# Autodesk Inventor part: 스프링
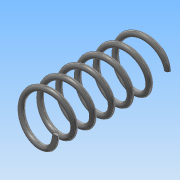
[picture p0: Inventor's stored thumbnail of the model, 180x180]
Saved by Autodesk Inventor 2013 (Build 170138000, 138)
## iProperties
Created: 2016-04
Part Number: 스프링
Material: 강철, 탄소
Document SubType Name: Modeling
Designer: Administrator
Density: 7.87 g/cm^3
Mass: 7.38127 g
Surface Area: 18.9917 cm^2
Volume: 0.937899 cm^3
Author: Administrator
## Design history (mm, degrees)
sketch "스케치1"
  geometry: L1 (0, 0)-(0, 42); L2 (0, 42)-(25.727, 42); C1 r 1 at (8, 0)
  constraints: 4 end point, 1 centre point, 1 horizontal alignment, 1 perpendicular, 1 vertical
  dimensions: "d0" = 42 distance of L1.start L1.end (derived); "d1" = 2 diameter of C1; "d2" = 16 diameter of C1.centre L1
feature "코일1" sketch "스케치1" pitch "d3" = 10; turns "d5" = 6; dims "d4" = 42 (= d0), "d6" = 0, angle "d7" = 90 deg, angle "d8" = 90 deg, "d9" = 0, "d10" = 0
sketch "스케치2"
  geometry: L1 (-10, 42)-(10, 42); L2 (10, 42)-(10, 0); L3 (10, 0)-(-10, 0); L4 (-10, 0)-(-10, 42); 2 further points
  constraints: 8 end point, 2 parallel, 1 coincident, 1 horizontal, 1 midpoint, 1 perpendicular
  dimensions: "d11" = 42 distance between parallel lines of L3 L1 (derived); "d13" = 20 distance between parallel lines of L2 L4
extrude "돌출1" sketch "스케치2" stored distance "d14" = 0; taper "d15" = 0 deg
node "솔리드1"
